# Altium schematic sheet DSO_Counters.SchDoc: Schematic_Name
size A4; CompanyName: University of Melbourne; DrawnBy: Student_#; Engineer: Your Name Here; Organization: University of Melbourne; DocumentNumber: 5; Revision: 0.1; SheetNumber: 5; SheetTotal: 10; Title_Project: Project_Title
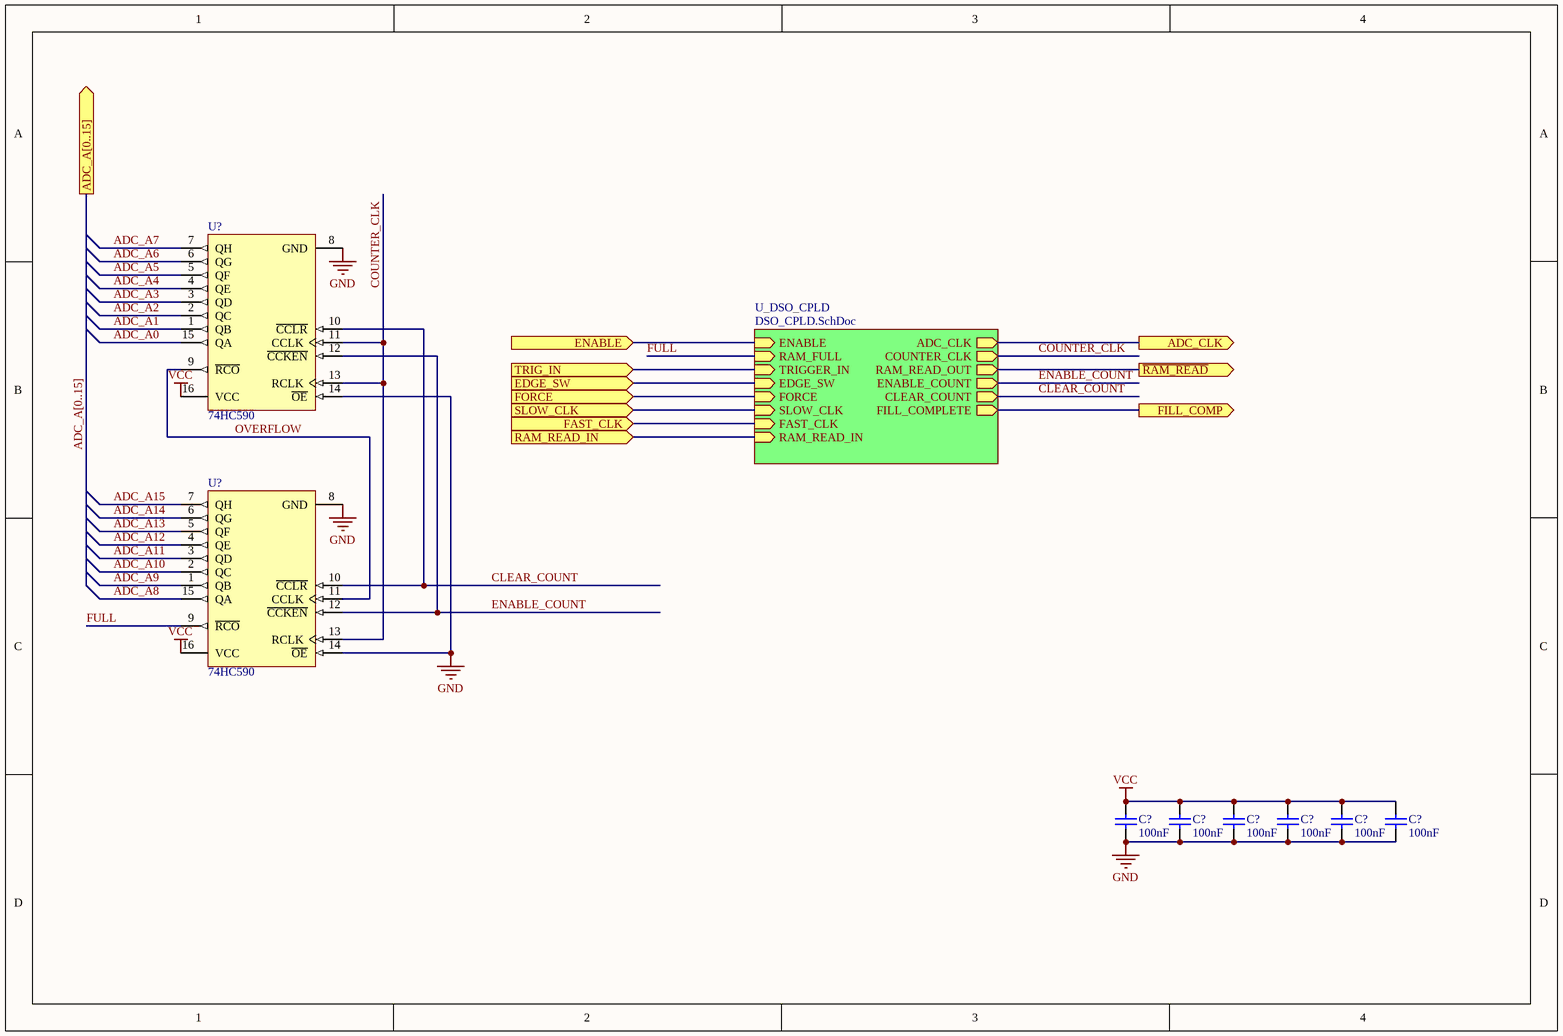
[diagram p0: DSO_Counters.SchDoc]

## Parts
(Parts that share a designator on the sheet are numbered #1, #2 ... from top to bottom, then left to right.)
C?#1  100nF  [0805C]
C?#2  100nF  [0805C]
C?#3  100nF  [0805C]
C?#4  100nF  [0805C]
C?#5  100nF  [0805C]
C?#6  100nF  [0805C]
U?#1  74HC590  [SOIC-16]
U?#2  74HC590  [SOIC-16]

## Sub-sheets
U_DSO_CPLD = DSO_CPLD.SchDoc: ENABLE (in), RAM_FULL (in), TRIGGER_IN (in), EDGE_SW (in), FORCE (in), SLOW_CLK (in), FAST_CLK (in), RAM_READ_IN (in), ADC_CLK (out), COUNTER_CLK (out), RAM_READ_OUT (out), ENABLE_COUNT (out), CLEAR_COUNT (out), FILL_COMPLETE (out)

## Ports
ADC_A[0..15] (out), ADC_CLK (out), EDGE_SW (in), ENABLE (in), FAST_CLK (in), FILL_COMP (out), FORCE (in), RAM_READ_IN (in), SLOW_CLK (in), TRIG_IN (in), ~{RAM_READ} (out)

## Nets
GND: C?#1.2 C?#2.2 C?#3.2 C?#4.2 C?#5.2 C?#6.2 U?#1.8(GND) U?#1.14(~{OE}) U?#2.8(GND) U?#2.14(~{OE})
VCC: C?#1.1 C?#2.1 C?#3.1 C?#4.1 C?#5.1 C?#6.1 U?#1.16(VCC) U?#2.16(VCC)
ADC_A0: U?#1.15(QA)
ADC_A1: U?#1.1(QB)
ADC_A2: U?#1.2(QC)
ADC_A3: U?#1.3(QD)
ADC_A4: U?#1.4(QE)
ADC_A5: U?#1.5(QF)
ADC_A6: U?#1.6(QG)
ADC_A7: U?#1.7(QH)
ADC_A8: U?#2.15(QA)
ADC_A9: U?#2.1(QB)
ADC_A10: U?#2.2(QC)
ADC_A11: U?#2.3(QD)
ADC_A12: U?#2.4(QE)
ADC_A13: U?#2.5(QF)
ADC_A14: U?#2.6(QG)
ADC_A15: U?#2.7(QH)
ADC_CLK: port ADC_CLK, sheet U_DSO_CPLD/ADC_CLK
CLEAR_COUNT: U?#1.10(~{CCLR}) U?#2.10(~{CCLR}) ; sheet U_DSO_CPLD/CLEAR_COUNT
COUNTER_CLK: U?#1.11(CCLK) U?#1.13(RCLK) U?#2.13(RCLK) ; sheet U_DSO_CPLD/COUNTER_CLK
EDGE_SW: port EDGE_SW, sheet U_DSO_CPLD/EDGE_SW
ENABLE: port ENABLE, sheet U_DSO_CPLD/ENABLE
ENABLE_COUNT: U?#1.12(~{CCKEN}) U?#2.12(~{CCKEN}) ; sheet U_DSO_CPLD/ENABLE_COUNT
FAST_CLK: port FAST_CLK, sheet U_DSO_CPLD/FAST_CLK
FILL_COMP: port FILL_COMP, sheet U_DSO_CPLD/FILL_COMPLETE
FORCE: port FORCE, sheet U_DSO_CPLD/FORCE
FULL: U?#2.9(~{RCO}) ; sheet U_DSO_CPLD/RAM_FULL
OVERFLOW: U?#1.9(~{RCO}) U?#2.11(CCLK)
~{RAM_READ}: port ~{RAM_READ}, sheet U_DSO_CPLD/RAM_READ_OUT
RAM_READ_IN: port RAM_READ_IN, sheet U_DSO_CPLD/RAM_READ_IN
SLOW_CLK: port SLOW_CLK, sheet U_DSO_CPLD/SLOW_CLK
TRIG_IN: port TRIG_IN, sheet U_DSO_CPLD/TRIGGER_IN

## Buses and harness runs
bus ADC_A[0..15] = port ADC_A[0..15]

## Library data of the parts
C?#1-C?#6 = C: Capacitor; Reviewed by: RM - 2018/08/05
U?#1 U?#2 = 74HC590: 8-Bit Binary Counter Register; Reviewed by: RM - 2018/08/05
